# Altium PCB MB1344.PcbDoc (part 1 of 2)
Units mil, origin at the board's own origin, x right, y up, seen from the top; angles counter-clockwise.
Board outline 2760.94 x 3253.06 mil, 2 copper layers (Top Layer, Bottom Layer), stack 61.811 mil thick; 133 components, 124 nets, 521 pads, 490 vias.
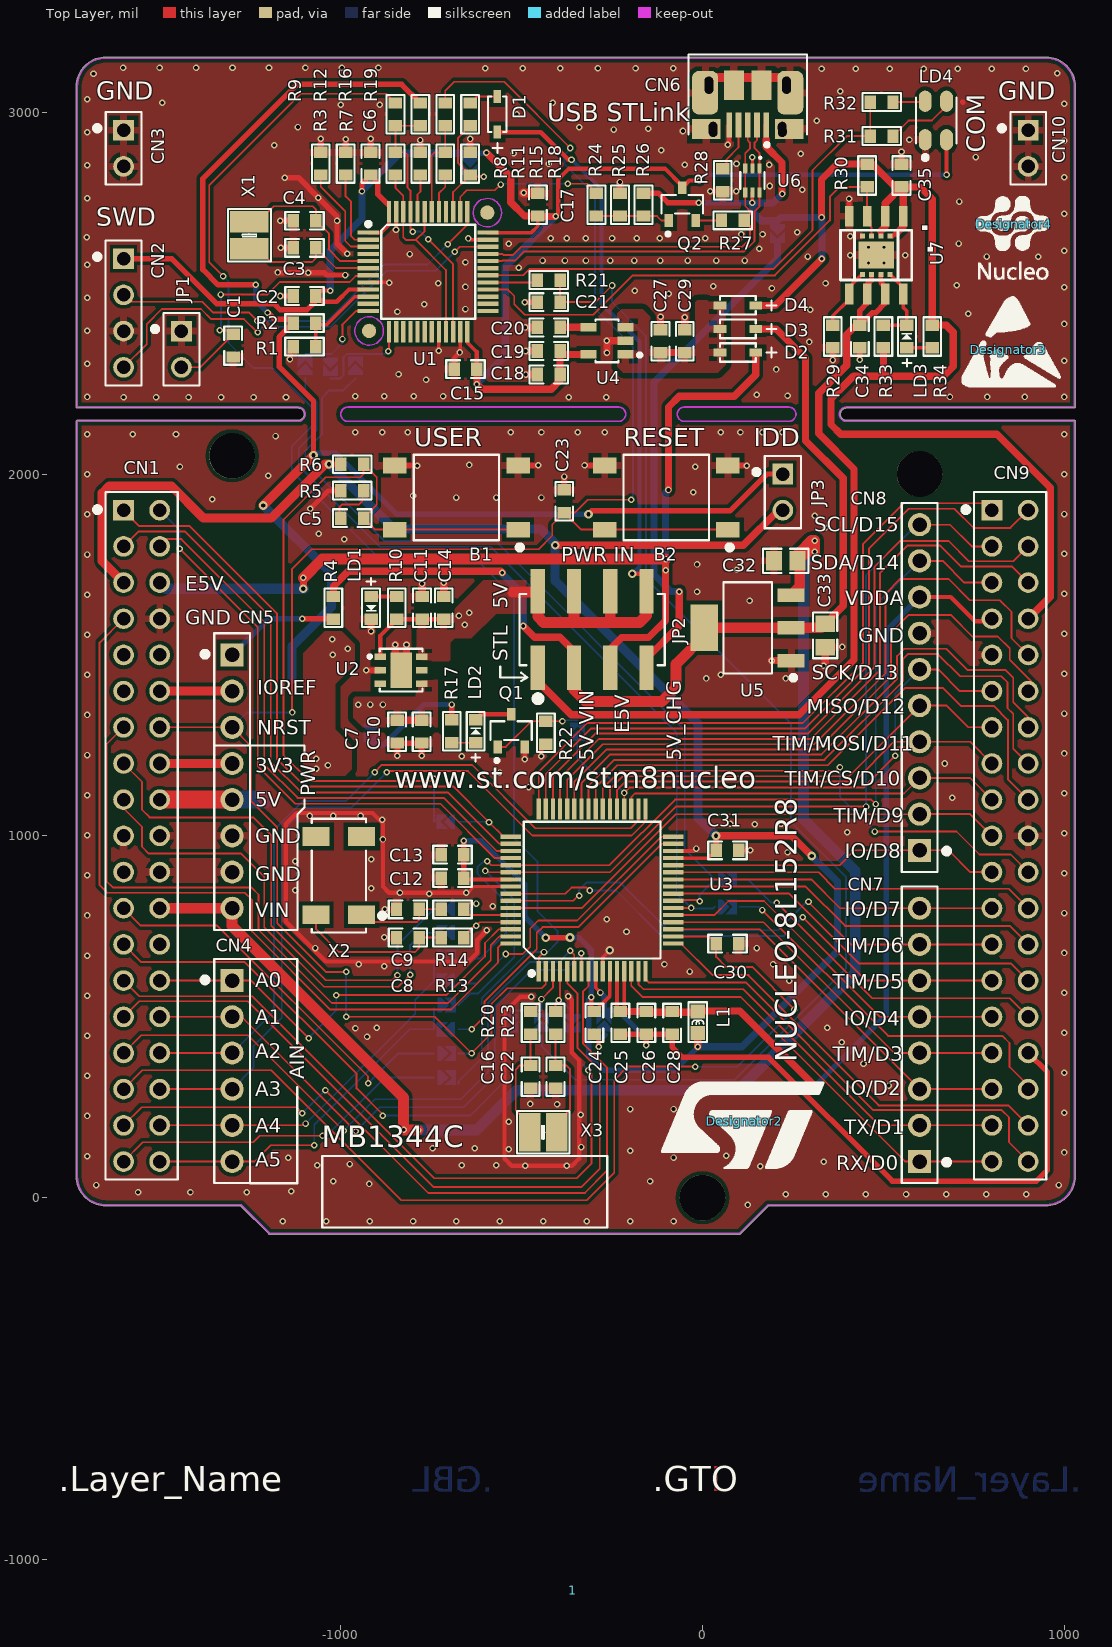
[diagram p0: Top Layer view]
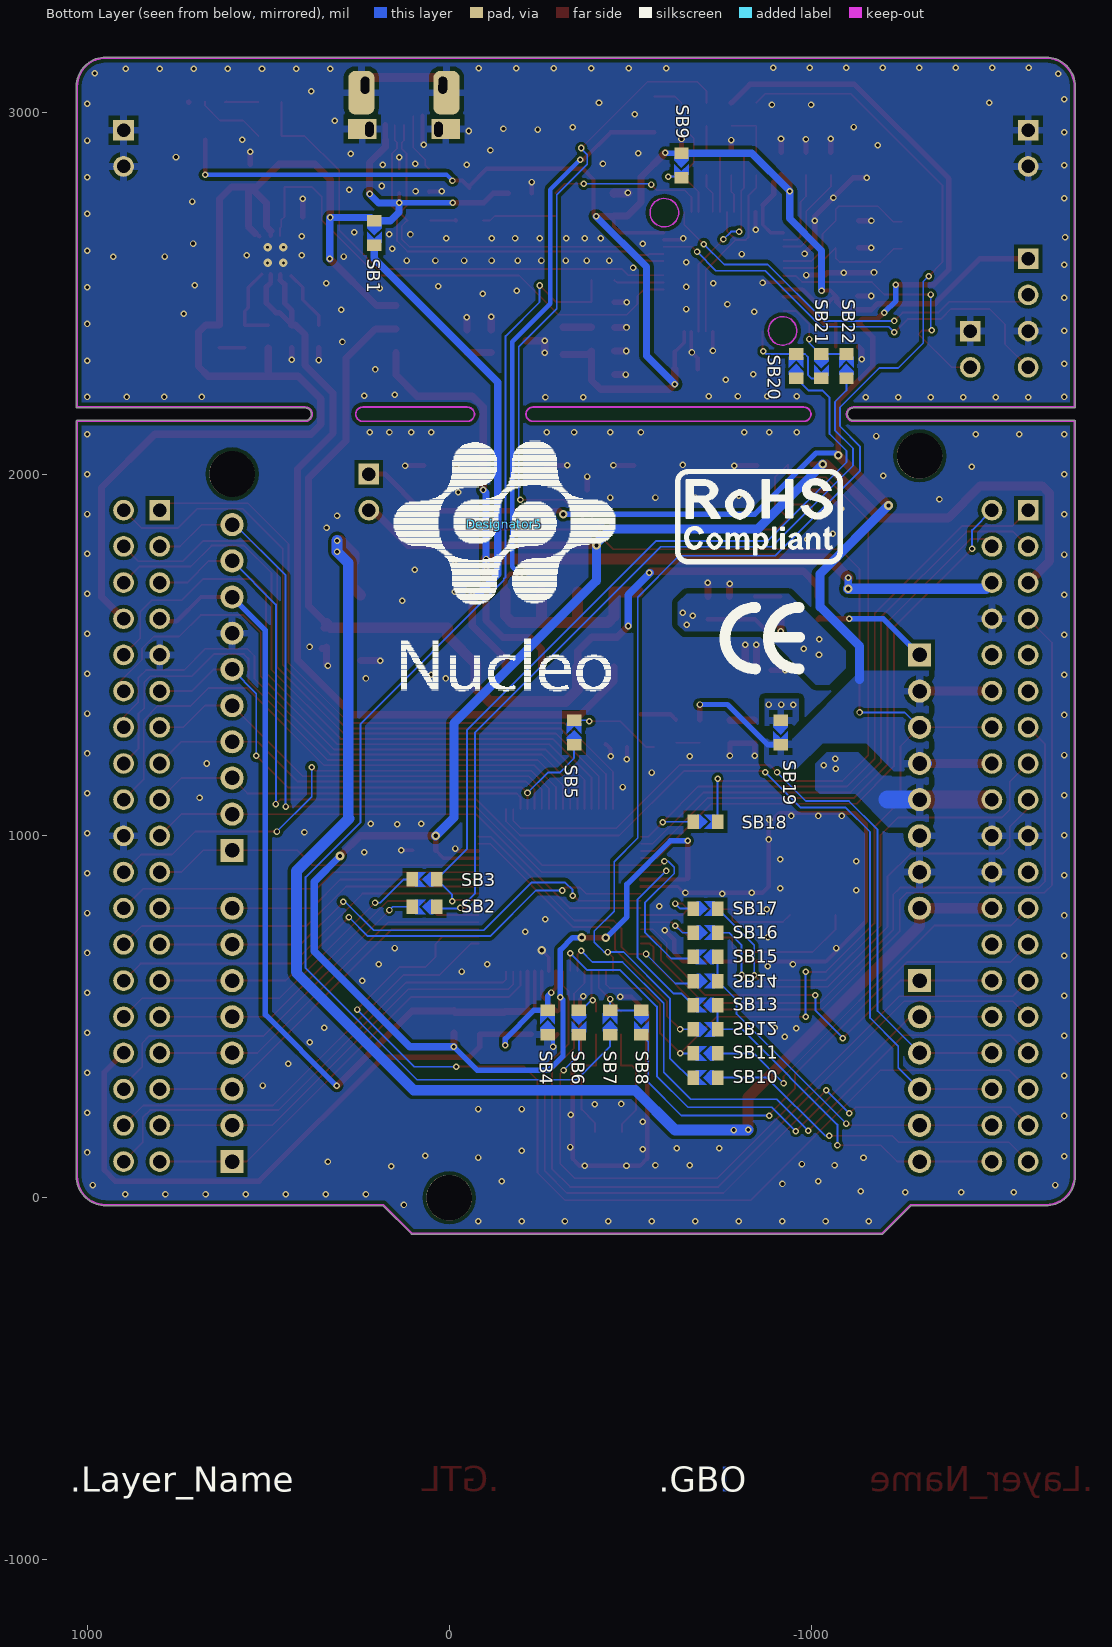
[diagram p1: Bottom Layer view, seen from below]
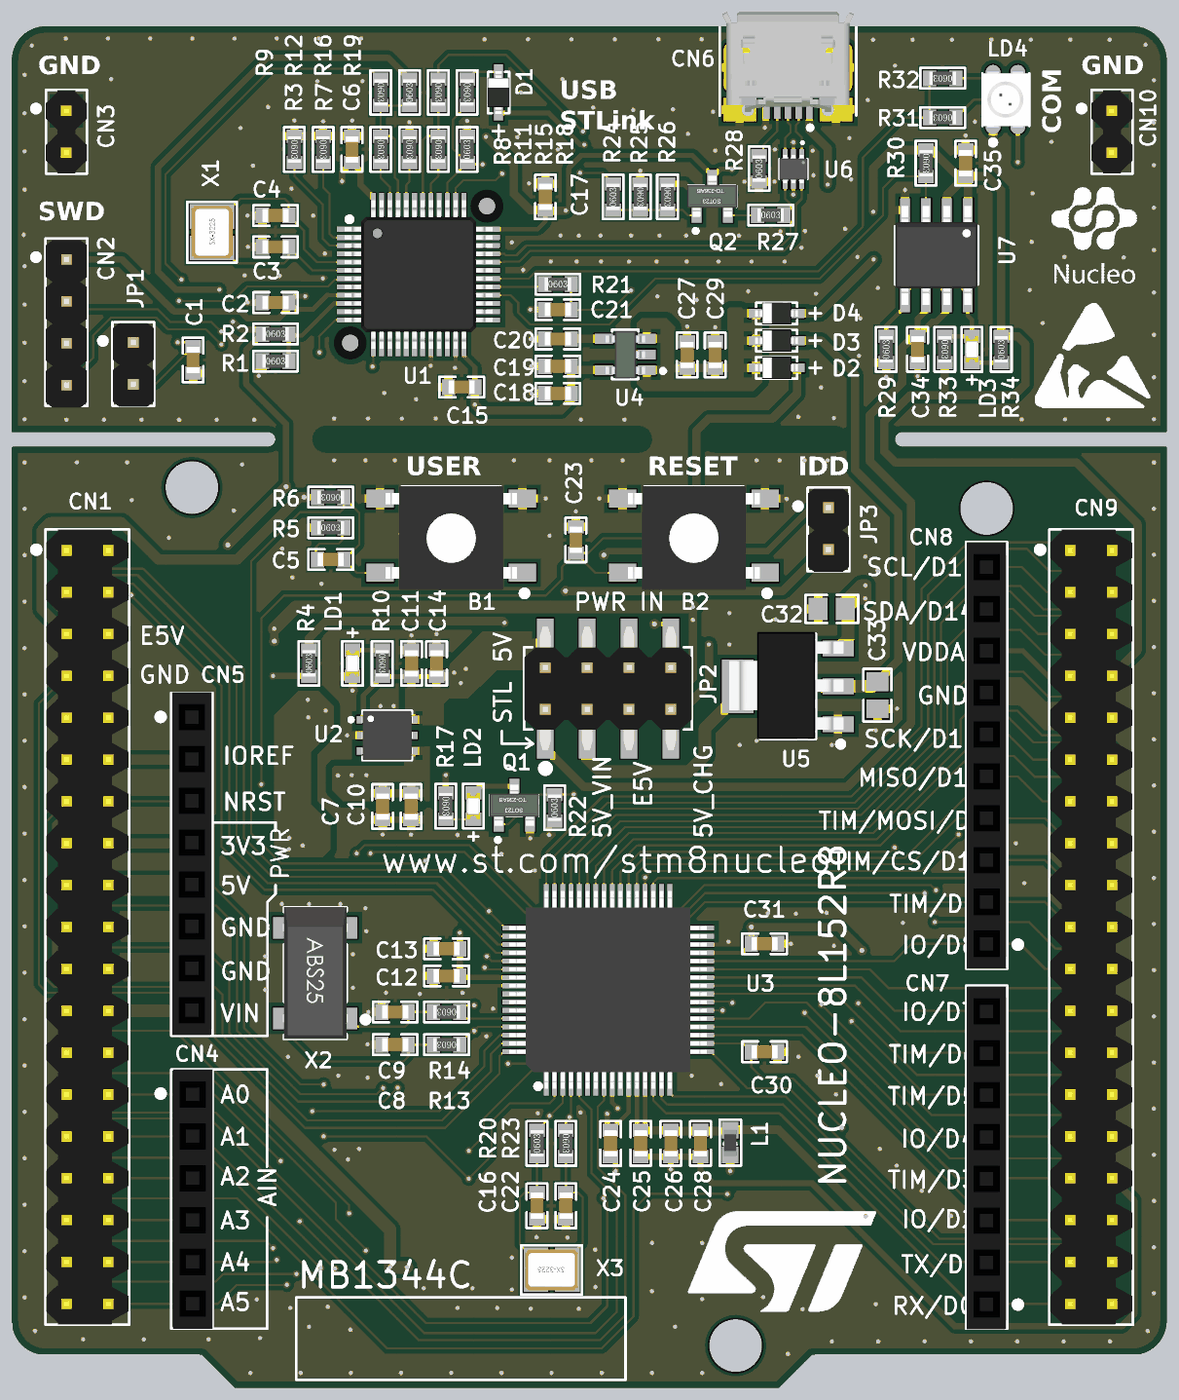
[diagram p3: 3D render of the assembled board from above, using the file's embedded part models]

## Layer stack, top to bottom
Top Solder: solder mask 0.5906, Solder Resist, Dk 3.5
Top Layer: signal copper 1.378
Dielectric 1: dielectric 59.0551, FR-4, Dk 4.8
Bottom Layer: signal copper 1.378
Bottom Solder: solder mask 0.5906, Solder Resist, Dk 3.5

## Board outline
-1730.47,59.05 ccw(c-1649.21,59.05) -1649.21,-22.2 ccw(c-1649.21,-19.69) -1649.17,-22.2 -1276.24,-22.2 -1198.24,-100.2 ccw(c-1196.46,-98.43) -1196.46,-100.94 102.76,-100.94 ccw(c102.76,-98.43) 104.53,-100.2 104.54,-100.19 cw(c102.76,-98.43) 104.52,-100.21 182.54,-22.2 949.21,-22.2 ccw(c949.21,59.06) 1030.47,59.06 1030.47,2145.67 ccw(c1027.95,2145.67) 1027.95,2148.18 398.03,2148.18 cw(c398.03,2165.35) 398.03,2182.52 1027.93,2182.52 ccw(c1027.95,2185.04) 1030.47,2185.04 1030.47,3070.87 ccw(c949.21,3070.87) 949.24,3152.12 ccw(c949.21,3070.87) 949.21,3152.12 cw(c949.21,3149.61) 949.24,3152.12 949.21,3152.12 -1649.21,3152.12 ccw(c-1649.21,3149.61) -1649.24,3152.12 cw(c-1649.21,3070.87) -1649.21,3152.12 -1649.24,3152.12 ccw(c-1649.21,3070.87) -1730.47,3070.87 -1730.47,2185.04 ccw(c-1727.95,2185.04) -1727.92,2182.52 -1117.72,2182.52 cw(c-1117.72,2165.35) -1100.55,2165.35 cw(c-1117.72,2165.35) -1117.72,2148.18 -1727.95,2148.18 ccw(c-1727.95,2145.67) -1730.47,2145.65

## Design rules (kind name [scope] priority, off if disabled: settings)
Clearance [All] p1: gap=7.87 ignorepadtopadclearanceinfootprint=FALSE except(0: Arc-Hole Track-Hole SMDPad-Hole THPad-Hole Via-Hole Fill-Hole Poly-Hole Region-Hole Text-Hole; 7: Region-Region; 8: Via-Poly; 10: Arc-Poly Arc-Region Track-Poly Track-Region SMDPad-Region THPad-Poly THPad-Region Via-Region Fill-Region Poly-Region; 12: SMDPad-Poly; 15: Fill-Poly Poly-Poly)
ComponentClearance [All] p1: gap=7.87 collisioncheckmode=3 verticalgap=7.87 showdistances=FALSE
DiffPairsRouting DiffPair_usb [InDifferentialPair('DifferentialPair1')] p1: maxlimit=10 minlimit=5 mostfreqgap=8 toplayer_minwidth=4 toplayer_maxwidth=6 toplayer_prefwidth=5 bottomlayer_minwidth=4 bottomlayer_maxwidth=6 bottomlayer_prefwidth=5 maxuncoupledlength=500
HoleSize [All] p1: absolutevalues=TRUE maxlimit=393.7 minlimit=1 maxpercent=80.000 minpercent=20.000
MatchedLengths DiffPair_usb_1 [InDifferentialPair ('NewDifferentialPair1')] p1: tolerance=50 checknetsindiffpair=TRUE checkdiffpairvsdiffpair=FALSE checkxsignals=FALSE checkothers=FALSE
MinimumSolderMaskSliver [All] p1: minsoldermaskwidth=0.8
PlaneConnect [All] p1: planeconnectstyle=Relief reliefexpansion=20 reliefentries=4 reliefconductorwidth=8.27 reliefairgap=8.27
PolygonConnect PolygonConnect_via [IsVia] p1: connectstyle=Direct reliefconductorwidth=10 reliefentries=4 polygonreliefangle="90 Angle" airgapwidth=10
PolygonConnect [All] p2: connectstyle=Relief reliefconductorwidth=20 reliefentries=4 polygonreliefangle="90 Angle" airgapwidth=12
RoutingVias [All] p1: holewidth=10 width=18 viastyle="Through Hole" minholewidth=8 minwidth=16 maxholewidth=12 maxwidth=24
SilkToSilkClearance [All] p1: silktosilkclearance=0
SilkToSolderMaskClearance [IsPad] p1: minsilkscreentomaskgap=1 clearancetoexposedcopper=TRUE
SolderMaskExpansion [All] p1: expansion=4
Width [All] p1: maxlimit=60 minlimit=5 preferedwidth=7.87 minimp=50.000000 maximp=50.000000 favimp=50.000000
23 further rules are at their usual default settings.

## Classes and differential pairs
net class PG[0..7]: PG0 PG1 PG2 PG3 PG4 PG5 PG6 PG7
net class PF[0..7]: PF0 PF1 PF4 PF5 PF6 PF7
net class PE[0..7]: PE0 PE1 PE2 PE3 PE4 PE5 PE6 PE7
net class PD[0..7]: PD0 PD1 PD2 PD3 PD4 PD5 PD6 PD7
net class PC[0..7]: PC0 PC1 PC2 PC3 PC4 PC5 PC6 PC7
net class PB[0..7]: PB0 PB1 PB2 PB3 PB4 PB5 PB6 PB7
net class PA[0..7]: PA0 PA1 PA2 PA3 PA4 PA5 PA6 PA7
component class "U_STM8L152R8T6 microcontroller power": C12 C13 C24 C25 C26 C28 C30 C31 L1 SB4
component class "U_STM8L152R8T6 microcontroller IOs": B1 B2 C5 C8 C9 C16 C22 C23 R5 R6 R13 R14 R20 R23 SB2 SB3 SB7 SB10 SB11 SB18 U3 X2 X3
component class U_ST-LinkV2_SWIM: C1 C2 C3 C4 C6 C15 C17 C18 C19 C20 C21 C27 C29 C34 C35 CN2 CN3 CN6 CN10 D1 D2 D3 D4 HW1 JP1 LD3 LD4 Q2 R1 R2 R3 R7 R8 R9 R11 R12 R15 R16 R18 R19 R21 R24 R25 R26 R27 R28 R29 R30 R31 R32 R33 R34 SB1 SB9 SB20 SB21 SB22 U1 U4 U6 U7 X1
component class U_Power: C7 C10 C11 C14 C32 C33 HW2 HW3 JP2 JP3 LD1 R10 SB19 U2 U5 U7
component class U_Arduino_extension_connectors: CN1 CN4 CN5 CN7 CN8 CN9 LD2 Q1 R4 R17 R22 SB5 SB6 SB8 SB12 SB13 SB14 SB15 SB16 SB17
component class Project_Overview: PCB
differential pair DifferentialPair1: +STLINK_USB_D_P -STLINK_USB_D_N

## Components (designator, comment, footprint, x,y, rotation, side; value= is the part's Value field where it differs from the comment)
1 "Comment" Sheetbox_2L2S -2134,-1295 r0 top
B1 "USER[BLUE]" SW4P600X600 -680,1935 r180 top
B2 "RESET[BLACK]" SW4P600X600 -100,1935 r180 top locked
C1 "C" C0603 -1297,2355 r90 top
C2 "C" C0603 -1100,2492 r0 top
C3 "C" C0603 -1100,2625 r180 top
C4 "C" C0603 -1100,2700 r180 top
C5 "C" C0603 -968,1878 r0 top
C6 "C" C0603 -917.33,2858 r270 top
C7 "C" C0603 -844,1288 r90 top
C8 "C" C0603 -814,719 r0 top
C9 "C" C0603 -814,797 r0 top
C10 "C" C0603 -776,1288 r90 top
C11 "C" C0603 -775,1630 r270 top
C12 "C" C0603 -691,883 r180 top
C13 "C" C0603 -691,948 r180 top
C14 "C" C0603 -715,1630 r270 top
C15 "C" C0603 -655,2290 r0 top
C16 "12PF" C0603 -475,334 r90 top
C17 "C" C0603 -455,2744.5 r270 top
C18 "C" C0603 -425,2275 r0 top
C19 "C" C0603 -425,2340 r0 top
C20 "C" C0603 -425,2405 r0 top
C21 "C" C0603 -425,2475 r0 top
C22 "12PF" C0603 -406,334 r90 top
C23 "C" C0603 -382,1925 r270 top
C24 "C" C0603 -299,482.97 r270 top
C25 "C" C0603 -227,482.97 r270 top
C26 "C" C0603 -155,482.97 r270 top
C27 "C" C0603 -116,2367 r270 top
C28 "C" C0603 -84,482.97 r270 top
C29 "C" C0603 -49,2367 r270 top
C30 "C" C0603 69,702 r0 top
C31 "C" C0603 69,960 r0 top
C32 "C" C0805 230,1760 r0 top
C33 "C" C0805 339,1554 r90 top
C34 "C" C0603 435,2380 r90 top
C35 "C" C0603 550,2825 r90 top
CN1 "2.54mm 2x19" HDRV38W64P254_2X19_4826X508X838P -1550,1000 r270 top locked
CN2 "SIP4" HDRV4W64P254_1X4_1016X254X854P -1600,2445 r270 top
CN3 "2.54mm 1X2" HDRV2W64P254_1X2_508X250X854P -1600,2900 r270 top
CN4 "SIP6" SOKV2W64P254_1X6_1574X250X850P -1300,350 r270 top locked
CN5 "SIP8" SOKV2W64P254_1X8_2082X250X850P -1300,1150 r270 top locked
CN6 "MICROUSB5_6" USB-MICRO-B-5P-SMD_800X560 125,2965 r180 top locked
CN7 "SIP8" SOKV2W64P254_1X8_2082X250X850P 600,450 r90 top locked
CN8 "SIP10" SOKV2W64P254_1X10_2590X250X850P 600,1410 r90 top locked
CN9 "2.54mm 2x19" HDRV38W64P254_2X19_4826X508X838P 850,1000 r270 top locked
CN10 "2.54mm 1X2" HDRV2W64P254_1X2_508X250X854P 900,2900 r270 top
D1 "D" SOD323 -567,2994 r270 top
D2 "D" SOD323 98,2336 r0 top
D3 "D" SOD323 98,2401 r0 top
D4 "D" SOD323 98,2466 r0 top
Designator1 "Comment" FIGURE_CROSS -4103,-2909 r0 top
Designator2 "Comment" ST_LOGO_10mm 116,211 r0 top
Designator3 "Comment" "LOGO ESD" 845,2344 r0 top
Designator4 "Comment" "NUCLEO_black 0.5cm" 860,2690 r0 top
Designator5 "Comment" "NUCLEO_black 2cm" -152,1861 r180 bottom
JP1 "SIP2" HDRV2W64P254_1X2_508X254X854P -1440,2345 r270 top locked
JP2 "2.54mm 2x4" HDRVS8W64P254_2X4_1016X750X850P -305,1570 r0 top locked
JP3 "SIP2" HDRV2W64P254_1X2_508X254X854P 222,1950 r270 top
L1 "L" L0603 -13,485 r90 top
LD1 "LED_green" D0603 -916,1630 r90 top
LD2 "LED_green" D0603 -627,1289 r270 top
LD3 "LED_red" D0603 565,2380 r270 top
LD4 "LED4_RED/GRN" PLCC150P350X280X210-4N 645,2977 r90 top
Q1 "NMOS" TO-236 -529,1291 r90 top
Q2 "NPN" TO-236 -56,2746 r90 top
R1 "R" R0603 -1100,2352 r0 top
R2 "R" R0603 -1100,2417 r0 top
R3 "R" R0603 -1055,2858 r270 top
R4 "R" R0603 -1020,1630 r90 top
R5 "R" R0603 -968,1954 r0 top
R6 "R" R0603 -968,2027 r180 top
R7 "R" R0603 -986.17,2858 r270 top
R8 "R" R0603 -848.5,2858 r270 top
R9 "R" R0603 -848.5,2994 r270 top
R10 "R" R0603 -845,1630 r270 top
R11 "R" R0603 -779.67,2858 r270 top
R12 "R" R0603 -779.67,2994 r90 top
R13 "R" R0603 -691,719 r180 top
R14 "R" R0603 -691,797 r180 top
R15 "R" R0603 -710.83,2858 r270 top
R16 "R" R0603 -710.83,2994 r270 top
R17 "R" R0603 -693,1289 r270 top
R18 "R" R0603 -642,2858 r90 top
R19 "R" R0603 -642,2994 r270 top
R20 "R" R0603 -475,482.97 r90 top
R21 "R" R0603 -425,2536 r0 top
R22 "R" R0603 -433,1285 r90 top
R23 "R" R0603 -406,482.97 r270 top
R24 "R" R0603 -293,2744.5 r90 top
R25 "R" R0603 -228,2744.5 r270 top
R26 "R" R0603 -163,2744.5 r270 top
R27 "R" R0603 84,2701 r0 top
R28 "R" R0603 56,2812 r90 top
R29 "R" R0603 360,2380 r90 top
R30 "R" R0603 455,2825 r270 top
R31 "R" R0603 495,2934 r180 top
R32 "R" R0603 495,3028 r180 top
R33 "R" R0603 500,2380 r270 top
R34 "R" R0603 635,2380 r90 top
SB1 "SB_ON" JP2_SMD 207,2666 r90 bottom
SB2 "SB_OFF" JP2_SMD 68,804 r180 bottom
SB3 "SB_OFF" JP2_SMD 68,879.53 r180 bottom
SB4 "SB_ON" JP2_SMD -272,483.75 r270 bottom
SB5 "SB_ON" JP2_SMD -345,1286 r270 bottom
SB6 "SB_OFF" JP2_SMD -358.33,483.75 r90 bottom
SB7 "SB_ON" JP2_SMD -444.67,483.75 r270 bottom
SB8 "SB_OFF" JP2_SMD -531,483.75 r90 bottom
SB9 "SB_OFF" JP2_SMD -642,2853 r90 bottom
SB10 "SB_ON" JP2_SMD -708,332 r180 bottom
SB11 "SB_ON" JP2_SMD -708,398.71 r180 bottom
SB12 "SB_ON" JP2_SMD -708,465.43 r0 bottom
SB13 "SB_OFF" JP2_SMD -708,532.14 r180 bottom
SB14 "SB_ON" JP2_SMD -708,598.86 r0 bottom
SB15 "SB_OFF" JP2_SMD -708,665.57 r180 bottom
SB16 "SB_OFF" JP2_SMD -708,732.28 r0 bottom
SB17 "SB_OFF" JP2_SMD -708,799 r0 bottom
SB18 "SB_ON" JP2_SMD -708,1039 r0 bottom
SB19 "SB_ON" JP2_SMD -916,1286 r90 bottom
SB20 "SB_ON" JP2_SMD -959,2298 r270 bottom
SB21 "SB_OFF" JP2_SMD -1028.5,2298 r90 bottom
SB22 "SB_ON" JP2_SMD -1098,2298 r270 bottom
U1 "STM32F103CBT6" QFP50P900X900X160-48N -758,2559 r0 top locked
U2 "LDL112PV33R" DFN300X300X80-7N -833,1458 r0 top
U3 "STM8L152R8T6" QFP50P1000X1000X160-64N -305,850 r90 top locked
U4 "LD3985M33R" SOT23-5 -264,2368 r180 top
U5 "LD1117S50TR" SOT-223 125,1575 r180 top
U6 "USBLC6-2P6" SOT-666 138,2811 r270 top
U7 "ST890" SOIC127P600X175-8N+PQFN65P300X300X90_HS-9N 480,2605 r270 top
X1 "X" XTAL320X250X100N -1252,2660 r90 top
X2 "MC306" OSCCC380X800X250-4N -1005,890 r180 top locked
X3 "8MHZ" XTAL320X250X100N -440,181 r180 top

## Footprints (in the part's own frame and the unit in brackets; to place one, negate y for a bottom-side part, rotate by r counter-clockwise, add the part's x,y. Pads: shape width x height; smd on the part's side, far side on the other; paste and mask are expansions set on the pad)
C0603 [mm]
  rect 0.8x0.95 smd mask+0.1: 1(-0.8,0) 2(0.8,0)
  Top Layer pour cut-out: -0.3,0.6 0.3,0.6 0.3,-0.6 -0.3,-0.6
  silkscreen extent -1.35,-0.63 1.35,0.63, body extent -0.8,-0.4 0.8,0.4, height 0.9
C0805 [mm] "Chip Capacitor, 2-Leads, Body 2.00x1.25mm, IPC Medium Density"
  rect 1.15x1.35 smd mask+0.1: 1(-0.825,0) 2(0.825,0)
  silkscreen extent -1.6,-0.85 1.6,0.85, body extent -1.05,-0.67 1.05,0.67, height 1.35
D0603 [mm]
  rect 0.8x0.95 smd mask+0.1: 1(-0.8,0) 2(0.8,0)
  Top Layer pour cut-out: -0.3,0.6 0.3,0.6 0.3,-0.6 -0.3,-0.6
  silkscreen extent -1.35,-0.63 2.1,0.63, body extent -0.8,-0.4 0.8,0.4, height 0.6
DFN300X300X80-7N [mm]
  rect 0.8x0.45 smd mask+0.1: 1(-1.45,0.95) 2(-1.45,0) 3(-1.45,-0.95) 4(1.45,-0.95) 5(1.45,0) 6(1.45,0.95)
  rect 1.5x2.5 smd mask+0.1: 7(0,0)
  silkscreen extent -2.25,-1.5 1.5,1.5, body extent -1.55,-1.5 1.55,1.5, height 0.75
FIGURE_CROSS [mil]
HDRV2W64P254_1X2_508X250X854P [mm]
  rect 1.45x1.45 hole 0.95 mask+0.1: 1(-1.27,0)
  round 1.45 hole 0.95 mask+0.1: 2(1.27,0)
  silkscreen extent -2.54,-2.01 2.54,1.25, body extent -2.54,-1.25 2.54,1.25, height 8.5
HDRV2W64P254_1X2_508X254X854P [mm]
  rect 1.45x1.45 hole 0.95 mask+0.1: 1(-1.27,0)
  round 1.45 hole 0.95 mask+0.1: 2(1.27,0)
  silkscreen extent -2.54,-2.01 2.54,1.27, body extent -2.49,-1.25 2.59,1.25, height 8.6
HDRV4W64P254_1X4_1016X254X854P [mm]
  rect 1.45x1.45 hole 0.95 mask+0.1: 1(-3.81,0)
  round 1.45 hole 0.95 mask+0.1: 2(-1.27,0) 3(1.27,0) 4(3.81,0)
  silkscreen extent -5.08,-2.01 5.08,1.27, body extent -4.98,-1.25 5.18,1.25, height 8.6
HDRV38W64P254_2X19_4826X508X838P [mm]
  rect 1.45x1.45 hole 0.95 mask+0.1: 1(-22.86,-1.27)
  round 1.45 hole 0.95 mask+0.1: 2(-22.86,1.27) 3(-20.32,-1.27) 4(-20.32,1.27) 5(-17.78,-1.27) 6(-17.78,1.27) 7(-15.24,-1.27) 8(-15.24,1.27) 9(-12.7,-1.27) 10(-12.7,1.27) 11(-10.16,-1.27) 12(-10.16,1.27) 13(-7.62,-1.27) 14(-7.62,1.27) 15(-5.08,-1.27) 16(-5.08,1.27) 17(-2.54,-1.27) 18(-2.54,1.27) 19(0,-1.27) 20(0,1.27) 21(2.54,-1.27) 22(2.54,1.27) 23(5.08,-1.27) 24(5.08,1.27) 25(7.62,-1.27) 26(7.62,1.27) 27(10.16,-1.27) 28(10.16,1.27) 29(12.7,-1.27) 30(12.7,1.27) 31(15.24,-1.27) 32(15.24,1.27) 33(17.78,-1.27) 34(17.78,1.27) 35(20.32,-1.27) 36(20.32,1.27) 37(22.86,-1.27) 38(22.86,1.27)
  silkscreen extent -24.13,-3.28 24.13,2.54, body extent -24.13,-2.5 24.13,2.5, height 8.5
HDRVS8W64P254_2X4_1016X750X850P [mm]
  rect 1x3.12 smd paste+0 mask+0.1: 1(-3.81,-2.69) 2(-3.81,2.69) 3(-1.27,-2.69) 4(-1.27,2.69) 5(1.27,-2.69) 6(1.27,2.69) 7(3.81,-2.69) 8(3.81,2.69)
  silkscreen extent -5.1,-5.06 5.1,2.5, body extent -5.08,-3.75 5.08,3.75, height 9.8
JP2_SMD [mil]
  rect 32x40 smd mask+3.94: 1(33.75,0) 2(-33.75,0)
  Top Layer region: 23.75,20 13.75,20 -6.25,0 13.75,-20 23.75,-20
  Top Layer region: -26.25,0 -16.25,0 3.75,20 -26.25,20
  Top Layer region: -26.25,0 -16.25,0 3.75,-20 -26.25,-20
L0603 [mm]
  rect 1x1 smd mask+0.1: 1(-0.75,0) 2(0.75,0)
  silkscreen extent -1.4,-0.65 1.4,0.65, body extent -0.8,-0.4 0.8,0.4, height 0.8
"LOGO ESD" [mil]
  silkscreen extent -127,-102 144,145
"NUCLEO_black 0.5cm" [mil]
  silkscreen extent -105,-152 99,78
"NUCLEO_black 2cm" [mil]
  silkscreen extent -305,-461 307,229
OSCCC380X800X250-4N [mm]
  rect 1.9x1.3 smd mask+0.1: 1(-1.6,2.75) 2(-1.6,-2.75) 3(1.6,-2.75) 4(1.6,2.75)
  silkscreen extent -3.16,-4 1.9,4, body extent -2,-4 2,4, height 2.7
PLCC150P350X280X210-4N [mm]
  oval 1.5x0.9 smd mask+0.1: 1(-1.35,0.75) 2(1.35,0.75) 3(1.35,-0.75) 4(-1.35,-0.75)
  silkscreen extent -2.71,-1.45 1.6,1.4, body extent -1.75,-1.4 1.75,1.4, height 1.9
QFP50P900X900X160-48N [mm]
  round 1 smd mask+0.5: 0(-4.15,-4.15) 0(4.15,4.15)
  rect 1.5x0.3 smd mask+0.05: 1(-4.2,2.75) 2(-4.2,2.25) 3(-4.2,1.75) 4(-4.2,1.25) 5(-4.2,0.75) 6(-4.2,0.25) 7(-4.2,-0.25) 8(-4.2,-0.75) 9(-4.2,-1.25) 10(-4.2,-1.75) 11(-4.2,-2.25) 12(-4.2,-2.75) 25(4.2,-2.75) 26(4.2,-2.25) 27(4.2,-1.75) 28(4.2,-1.25) 29(4.2,-0.75) 30(4.2,-0.25) 31(4.2,0.25) 32(4.2,0.75) 33(4.2,1.25) 34(4.2,1.75) 35(4.2,2.25) 36(4.2,2.75)
  rect 0.3x1.5 smd mask+0.05: 13(-2.75,-4.2) 14(-2.25,-4.2) 15(-1.75,-4.2) 16(-1.25,-4.2) 17(-0.75,-4.2) 18(-0.25,-4.2) 19(0.25,-4.2) 20(0.75,-4.2) 21(1.25,-4.2) 22(1.75,-4.2) 23(2.25,-4.2) 24(2.75,-4.2) 37(2.75,4.2) 38(2.25,4.2) 39(1.75,4.2) 40(1.25,4.2) 41(0.75,4.2) 42(0.25,4.2) 43(-0.25,4.2) 44(-0.75,4.2) 45(-1.25,4.2) 46(-1.75,4.2) 47(-2.25,4.2) 48(-2.75,4.2)
  Keep-Out Layer circle w0.1: c4.15,4.15 r1
  Keep-Out Layer circle w0.1: c-4.15,-4.15 r1
  silkscreen extent -4.25,-3.3 3.3,3.4, body extent -4.5,-4.5 4.5,4.5, height 1.5
QFP50P1000X1000X160-64N [mm]
  rect 1.45x0.3 smd paste+0 mask+0.05: 1(-5.7,3.75) 2(-5.7,3.25) 3(-5.7,2.75) 4(-5.7,2.25) 5(-5.7,1.75) 6(-5.7,1.25) 7(-5.7,0.75) 8(-5.7,0.25) 9(-5.7,-0.25) 10(-5.7,-0.75) 11(-5.7,-1.25) 12(-5.7,-1.75) 13(-5.7,-2.25) 14(-5.7,-2.75) 15(-5.7,-3.25) 16(-5.7,-3.75) 33(5.7,-3.75) 34(5.7,-3.25) 35(5.7,-2.75) 36(5.7,-2.25) 37(5.7,-1.75) 38(5.7,-1.25) 39(5.7,-0.75) 40(5.7,-0.25) 41(5.7,0.25) 42(5.7,0.75) 43(5.7,1.25) 44(5.7,1.75) 45(5.7,2.25) 46(5.7,2.75) 47(5.7,3.25) 48(5.7,3.75)
  rect 0.3x1.45 smd paste+0 mask+0.05: 17(-3.75,-5.7) 18(-3.25,-5.7) 19(-2.75,-5.7) 20(-2.25,-5.7) 21(-1.75,-5.7) 22(-1.25,-5.7) 23(-0.75,-5.7) 24(-0.25,-5.7) 25(0.25,-5.7) 26(0.75,-5.7) 27(1.25,-5.7) 28(1.75,-5.7) 29(2.25,-5.7) 30(2.75,-5.7) 31(3.25,-5.7) 32(3.75,-5.7) 49(3.75,5.7) 50(3.25,5.7) 51(2.75,5.7) 52(2.25,5.7) 53(1.75,5.7) 54(1.25,5.7) 55(0.75,5.7) 56(0.25,5.7) 57(-0.25,5.7) 58(-0.75,5.7) 59(-1.25,5.7) 60(-1.75,5.7) 61(-2.25,5.7) 62(-2.75,5.7) 63(-3.25,5.7) 64(-3.75,5.7)
  silkscreen extent -5.95,-4.8 4.8,4.8, body extent -6,-6 6,6, height 1.56
R0603 [mm]
  rect 0.8x0.95 smd mask+0.1: 1(-0.8,0) 2(0.8,0)
  Top Layer pour cut-out: -0.3,0.6 0.3,0.6 0.3,-0.65 -0.3,-0.65
  silkscreen extent -1.35,-0.63 1.35,0.63, body extent -0.8,-0.4 0.8,0.4, height 0.45
Sheetbox_2L2S [mil] "Sheetbox 2 layers / 2 silkscreens"
  round 20 on Mech16: 1(813.78,210.69) 1(2736.9,210.69)
SOD323 [mm]
  rect 0.9x0.55 smd mask+0.1: 1(-1.25,0) 2(1.25,0)
  silkscreen extent -1.25,-0.65 2.7,0.65, body extent -1.3,-0.67 1.3,0.68, height 1.1
SOIC127P600X175-8N+PQFN65P300X300X90_HS-9N [mm]
  rect 1.45x0.6 smd: 1(-2.725,1.905) 2(-2.725,0.635) 3(-2.725,-0.635) 4(-2.725,-1.905) 5(2.725,-1.905) 6(2.725,-0.635) 7(2.725,0.635) 8(2.725,1.905)
  rect 0.35x0.35 smd: 1(-1.35,0.975) 2(-1.35,0.325) 3(-1.35,-0.325) 4(-1.35,-0.975) 5(1.35,-0.975) 6(1.35,-0.325) 7(1.35,0.325) 8(1.35,0.975)
  rect 1.9x2.5 smd: 9(0,0)
  silkscreen extent -1.75,-2.5 1.75,2.5, body extent -3,-2.5 3,2.5, height 1.75
SOKV2W64P254_1X6_1574X250X850P [mm]
  rect 1.62x1.62 hole 1.02 mask+0.1: 1(-6.35,0)
  round 1.62 hole 1.02 mask+0.1: 2(-3.81,0) 3(-1.27,0) 4(1.27,0) 5(3.81,0) 6(6.35,0)
  silkscreen extent -7.87,-2.08 7.87,1.25, body extent -7.87,-1.15 7.87,1.25, height 8.5
SOKV2W64P254_1X8_2082X250X850P [mm]
  rect 1.62x1.62 hole 1.02 mask+0.1: 1(-8.89,0)
  round 1.62 hole 1.02 mask+0.1: 2(-6.35,0) 3(-3.81,0) 4(-1.27,0) 5(1.27,0) 6(3.81,0) 7(6.35,0) 8(8.89,0)
  silkscreen extent -10.41,-2.08 10.41,1.25, body extent -10.45,-1.2 10.37,1.2, height 8.5
SOKV2W64P254_1X10_2590X250X850P [mm]
  rect 1.62x1.62 hole 1.02 mask+0.1: 1(-11.43,0)
  round 1.62 hole 1.02 mask+0.1: 2(-8.89,0) 3(-6.35,0) 4(-3.81,0) 5(-1.27,0) 6(1.27,0) 7(3.81,0) 8(6.35,0) 9(8.89,0) 10(11.43,0)
  silkscreen extent -12.95,-2.08 12.95,1.25, body extent -12.95,-1.2 12.95,1.2, height 8.5
SOT23-5 [mm]
  rect 1.1x0.6 smd mask+0.1: 1(-1.3,0.95) 2(-1.3,0) 3(-1.3,-0.95) 4(1.3,-0.95) 5(1.3,0.95)
  silkscreen extent -2.35,-1.5 0.8,1.5, body extent -1.21,-1.44 1.19,1.46, height 1.09
SOT-223 [mm]
  rect 1.9x0.95 smd mask+0.1: 1(-3.05,2.3) 2(-3.05,0) 3(-3.05,-2.3)
  rect 1.9x3.25 smd mask+0.1: 4(3.05,0)
  silkscreen extent -3.34,-3.2 1.7,3.65, body extent -3.38,-3.3 3.58,3.2, height 1.9
SOT-666 [mm]
  rect 0.7x0.3 smd mask+0.1: 1(-0.85,0.5) 2(-0.85,0) 3(-0.85,-0.5) 4(0.85,-0.5) 5(0.85,0) 6(0.85,0.5)
  silkscreen extent -1.65,-0.85 0.6,0.85, body extent -0.85,-0.85 0.85,0.85, height 0.6
ST_LOGO_10mm [mil]
  silkscreen extent -230,-130 220,110
SW4P600X600 [mm]
  rect 1.65x1.1 smd mask+0.1: 1(-4.325,2.25) 2(4.325,2.25) 3(4.325,-2.25) 4(-4.325,-2.25)
  silkscreen extent -4.61,-3 3,3.66, body extent -4,-3 4,3.3, height 7.3
TO-236 [mm]
  rect 0.9x0.6 smd mask+0.1: 1(-1.15,0.95) 2(-1.15,-0.95) 3(1.15,0)
  silkscreen extent -2.15,-1.45 0.65,1.45, body extent -1.25,-1.5 1.25,1.5, height 1.09
USB-MICRO-B-5P-SMD_800X560 [mm]
  rect 0.4x1.75 smd mask+0.1: 1(-1.3,0) 2(-0.65,0) 3(0,0) 4(0.65,0) 5(1.3,0)
  rect 2x1.4 hole 0.6 slot 1.05 at 90.65 deg copper offset -0.5,-0.02 paste+0 mask+0.1: 6(-2.425,0.32)
  rect 2x1.4 hole 0.6 slot 1.05 at 90.65 deg copper offset 0.5,-0.02 paste+0 mask+0.1: 7(2.425,0.32)
  rrect50% 1.825x3.05 hole 0.6 slot 1.2 at 90.7 deg copper offset -0.262,0.525 paste+0 mask+0.1: 8(-2.725,-2.78)
  rrect50% 1.825x3.05 hole 0.6 slot 1.2 at 90.7 deg copper offset 0.262,0.525 paste+0 mask+0.1: 9(2.725,-2.78)
  rect 1.4x2.1 smd paste+0 mask+0.1: 10(-0.975,-2.78) 11(0.975,-2.78)
  silkscreen extent -4.15,-4.95 4.15,1.51, body extent -3.99,-5.61 3.99,0.45, height 2.74
XTAL320X250X100N [mm]
  rect 1.5x2.7 smd mask+0.1: 1(-0.95,0) 2(0.95,0)
  silkscreen extent -1.85,-1.5 1.85,1.5, body extent -1.6,-1.25 1.6,1.25, height 0.81

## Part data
B1: library part 1010001100062, "tact switch,blue,6*6,SMT,180,CTSM-644B-V-T/R,(TD-0341X-GO0）"
B2: library part 1010001100063, "tact switch,black,6*6,SMT,180,CTSM-644N-V-T/R,(TD-0341X-A00）"
C1 C2 C5 C6 C7 C11 C12 C15 C17 C18 C23 C24 C25 C26 C29 C31 C34: library part 1004001100110, "CAP,100NF,+/-10%,X7R,50V,SMD0603"
C3 C4 C16 C22: library part 1004001100897, "CAP,12PF,+/-5%,NPO,50V,SMD0603"
C8 C9 C21: library part 1004001100069, "CAP,20PF,+/-5%,C0G,50V,SMD0603"
C10 C13 C14 C19 C27 C28 C30 C35: library part 1004001100120, "CAP,1UF,+/-10%,X7R,16V,SMD0603"
C20: library part 1004001100103, "CAP,10NF,+/-10%,X7R,50V,SMD0603"
C32 C33: library part 1004001100159, "CAP,10UF,+/-10%,X5R,16V,SMD0805"
CN1 CN9: library part 1009001200377, "Connector,Pin Header,Straight,Male,2.54MM pitch,2x19P,6.0mm,10mm,Au Over 50u\"NI, black,DIP"
CN2: library part 1009001200307, "Connector,Pin Header,Straight,Male,1x4Pin,2.54MM pitch,6.0,3.0,Au over 50 u nickle , black,DIP"
CN3 CN10: library part 1009001200378, "Connector,Pin Header,Straight,Male,2.54MM pitch,1x2P,6.0mm,10mm,Au Over 50u\"NI, black,DIP"
CN4: library part 1009002200189, "Connector,Pin Socket,Straight,Female,1x6Pin,2.54MM pitch,8.5,9.92,Gold Flash 1u, black,DIP"
CN5 CN7: library part 1009002200162, "Connector,Pin Socket,Straight,Female,1x8Pin,2.54MM pitch,8.5,9.92,Gold Flash 1u, black,DIP"
CN6: library part 1009007100040R2, "Connector,MicroUSB B port,5 Position,Right Angle,Gold Flash 1u, black,SMD"
CN8: library part 1009002200163, "Connector,Pin Socket,Straight,Female,1x10Pin,2.54MM pitch,8.5,9.92,Gold Flash 1u, black,DIP"
D1 D2 D3 D4: library part 1006002100076C, "DIODE SCHOTTKY,BAT60JFILM,10V,3A, SOD323/A,ST,(X3 Code 9151097)"
JP1 JP3: library part 1009001200085R1, "Connector,Pin Header,Straight,Male,1x2Pin,2.54MM pitch,6.0,3.0,Au over 50 u nickle , black,DIP"
JP2: library part 1009001100223, "Connector,Pin Header,Straight,Male,2x4Pin,2.54MM pitch,6.0mm,Gold Flash  Over NI,black,SMD"
L1: library part 1005005100118, "Ferrite Bead,600ohm@100MHz,+/-25%,1000mA,0.2ohm,SMD0603"
LD1 LD2: library part 1006001100094, "LED,Yellow-Green,Water clear,20mA,0603,573nm,Vf:2.0v;"
LD3: library part 1006001100139, "LED,Briliant Red,WATER CLEAR,0603 TR"
LD4: library part 1006001100098, "LED IND RED/GRN TOP MOUNT 4PLCC,3.2*2.8MM"
Q1: library part 1006015100003, "Mosfet,N-Channel,2N7002,60V,115mA,SOT-23,SMD"
Q2: library part 1006013100039, "Trans,NPN,MMBT9013G-I-AE3-R,Ic:500mA,Vceo:20v, SOT-23,SMD"
R1 R2 R6 R18: library part 1003001100221, "RES,4K7,+/-5%,1/10W,SMD0603"
R3 R7 R26 R30: library part 1003001100235, "RES,10K,+/-5%,1/10W,SMD0603"
R4 R34: library part 1003001100202, "RES,1K,+/-5%,1/10W,SMD0603"
R5 R21 R24: library part 1003001100186, "RES,100R,+/-5%,1/10W,SMD0603"
R8 R15: library part 1003001100192, "RES,220R,+/-5%,1/10W,SMD0603"
R9 R16: library part 1003001100178, "RES,47R,+/-5%,1/10W,SMD0603"
R10 R17: library part 1003001100424, "RES,510R,+/-5%,1/10W,SMD0603"
R11 R28 R33: library part 1003001100269, "RES,100K,+/-5%,1/10W,SMD0603"
R12: library part 1003001100200, "RES,680R,+/-5%,1/10W,SMD0603"
R13 R14 R20 R23: library part 1003001100161, "RES,0R,+/-5%,1/10W,SMD0603"
R19: library part 1003001100467, "RES,2K7,+/-1%,1/10W,SMD0603"
R22: library part 1003001100291, "RES,1M,+/-5%,1/10W,SMD0603"
R25: library part 1003001100368, "RES,36K, +/-1%,1/10W,SMD0603"
R27: library part 1003001100207, "RES,1K5,+/-5%,1/10W,SMD0603"
R29: library part 1003001100211, "RES,2K2,+/-1%,1/10W,SMD0603"
R31 R32: library part 1003001100196, "RES,330R,+/-5%,1/10W,SMD0603"
SB1 SB4 SB5 SB7 SB10 SB11 SB12 SB14 SB18 SB19 SB20 SB22: library part PN029, "RES,0R,+/-5%,1/10W,SMD0603"
SB2 SB3 SB6 SB8 SB9 SB13 SB15 SB16 SB17 SB21: library part PN034, "RES,0R,+/-5%,1/10W,SMD0603"
U1: library part 1002001100035C, "IC, ARM Cortex-M3 MCU,STM32F103CBT6,LQFP-48,SMD,TR,(9175111),customer supply"
U2: library part 1002006100237C, "IC,LDO,1.2 A low quiescent current LDO with reverse current protection 3.3V,LDL112PV33R,DFN3x3,SMD"
U3: library part 1002002100257C, "IC,MCU 8-bit 64KB FLASH 3.3V,STM8L152R8T6,LQFP64, SMD"
U4: library part 1002006100166C, "IC,LDO,3.3V,LD3985M33R,SOT23-5L,ST,(X3 Code 9176161)"
U5: library part 1002006100169C, "IC,LDO,5V,LD1117S50TR,SOT223,STMicroelectronics,9176133"
U6: library part 1002020100274C, "IC,ESD Protection for High Speed Interface Protection 2.5 PF Low Cap,USBLC6-2P6, SOT-666,SMD,TR"
U7: library part 1002004100103C, "IC PWR SWITCH,ST890CDR,SO-8,ST,(X3 Code 9172002)"
X1 X3: library part 1008002100145C, "CRYSTAL, 8pF, -+50PPM,NX3225GD-8MHz-EXS00A-CG04874,SMT"
X2: library part 1008002100059, "Crystal,ABS25-32.768KHZ-T,32.768KHz,+/-20PPM,12.5PF,8 x3.8MM,SMD"

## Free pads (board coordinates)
  round 125.98 hole 125.98 unplated: 0(-1300,2050) 0(0,0) 0(600,2000)

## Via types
v1: diameter 18, hole 10, Top Layer to Bottom Layer, tented both sides, 474 vias
v2: diameter 24, hole 12, Top Layer to Bottom Layer, tented both sides, 12 vias
v3: diameter 23.62, hole 7.87, Top Layer to Bottom Layer, 4 vias

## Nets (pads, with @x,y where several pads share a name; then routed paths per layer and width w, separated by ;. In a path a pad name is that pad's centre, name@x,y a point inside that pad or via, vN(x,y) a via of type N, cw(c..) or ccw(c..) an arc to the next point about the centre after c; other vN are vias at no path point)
3V3: CN1.12 CN1.16 CN5.2 CN5.4 JP3.1 R2.1 R12.2 R17.1 SB19.2 | length 4699.6
  Top Layer w15: v1(-1234.37,2522.63) -1338.63,2522.63 -1380.87,2564.87 -1380.87,2816.13 -1120,3077 -831.17,3077 R12.2@-779.67,3025.5 ; v1(-1202,2446) -1201,2446 -1183,2428 -1142.5,2428 R2.1@-1131.5,2417 -1170,2378.5 -1170,2297 -1075,2202 v2(-1075,2052) ; R17.1@-693,1320.5 v1(-693,1363) ; v2(-315,1889) -306,1898 76,1898 178,2000 JP3.1@222,2000
  Top Layer w25: CN1.16@-1500,1200 CN5.4@-1300,1200 ; CN1.12@-1500,1400 CN5.2@-1300,1400 ; v2(-1214,1913) v2(-1075,2052)
  Bottom Layer w15: v1(-1234.37,2522.63) -1234.37,2478.37 v1(-1202,2446) ; v2(-1075,2052) -1069,2058 -1014,2058 -845,1889 v2(-315,1889) ; SB19.2@-916,1252.25 -879.98,1252.25 -769.23,1363 v1(-693,1363)
  Bottom Layer w25: CN1.16@-1500,1200 CN1.16@-1489,1200 ; CN5.4@-1322,1200 CN5.4@-1300,1200 ; v2(-1214,1913) -1025,1724 -1025,1633 -1134,1524 -1134,1432
3V3_STLINK: C2.2 C6.2 C15.2 C17.2 C18.2 C19.2 CN2.1 LD4.4 Q2.3 SB9.1 U1.1 U1.9 U1.24 U1.36 U1.48 U4.5 | length 4718.7
  Top Layer w10: -977,2509.79 U1.9@-923.35,2509.79 ; U1.1@-923.35,2667.27 -887.73,2667.27 -866.27,2688.73 U1.48@-866.27,2724.35 -866.27,2742.27 U1.48@-867.86,2743.86 ; U1.24@-649.73,2393.65 -649.73,2363.73 -623.5,2337.5 ; U1.36@-592.65,2667.27 -472.73,2667.27 -455,2685 C17.2@-455,2713
  Top Layer w12: C2.2@-1068.5,2492 -1053.5,2507 v1(-1029,2507) ; C2.2@-1066,2492 -1050,2476 -1010.79,2476 -977,2509.79 ; C15.2@-623.5,2290 -623.5,2337.5 ; v1(-406,2712) -399,2719 -399,2814 -369,2844 -103.72,2844 -56,2796.28 Q2.3@-56,2791.28 -36.28,2811 v1(-9,2811) ; v1(674.53,2827.47) LD4.4@674.53,2923.85
  Top Layer w15: CN2.1@-1600,2595 -1467,2595 -1343,2471 -1184,2471 -1167,2454 -1093,2454 -1071.5,2475.5 C2.2@-1071.5,2486.5 ; v1(-941,2782) -941,2802.84 C6.2@-917.33,2826.5 -896.86,2806.03 -896.86,2772.86 U1.48@-867.86,2743.86
  Top Layer w20: C15.2@-623.5,2290 v1(-623.5,2248.5) -609,2234 -418,2234 -393.5,2258.5 C18.2@-393.5,2275 C19.2@-393.5,2340 -384.1,2330.6 U4.5@-315.18,2330.6 ; v1(-597,2888) -530,2821 -530,2751 -492,2713 C17.2@-455,2713 -454,2712 v1(-406,2712)
  Bottom Layer w12: v1(-9,2811) 7.47,2827.47 v1(674.53,2827.47)
  Bottom Layer w15: SB9.1@-642,2886.75 -598.25,2886.75 v1(-597,2888)
  Bottom Layer w20: v1(-1029,2507) -1029,2618 -941,2706 v1(-941,2782) -836.25,2886.75 SB9.1@-642,2886.75 ; v1(-623.5,2248.5) -545,2327.01 -545,2573 v1(-406,2712)
5V: C11.2 C14.2 CN1.18 CN5.5 D1.2 JP2.2 JP2.4 JP2.6 JP2.8 R10.2 U2.1 U2.6 | length 2775.8
  Top Layer w12: U2.1@-890.09,1495.4 -890.09,1553.42 R10.2@-845,1598.5 C11.2@-775,1598.5 C14.2@-715,1598.5 ; D1.2@-567,2944.79 -446.79,2944.79 -371,2869 v1(-362,2869) ; v2(-194,1724) -168,1724 -155,1711 JP2.8@-155,1674.33
  Top Layer w30: -524,1674 -523.67,1674.33 -455,1674.33 -455,1606 -439,1590 -355,1590 ; JP2.4@-355,1674.33 -355,1590 ; JP2.6@-255,1674.33 -255,1591 -254,1590 ; JP2.8@-155,1674.33 -155,1609 -174,1590 -254,1590 ; -355,1590 -254,1590
  Top Layer w50: CN1.18@-1500,1100 CN5.5@-1300,1100
  Bottom Layer w12: v1(-362,2869) -279,2786 -279,2470.84 -174,2365.84 -174,1744 v2(-194,1724)
  Bottom Layer w50: CN5.5@-1300,1100 -1211,1100
  other v1: -1068,1186 -1035,1195 -1067,1213 -1022,1501 -980,1517 -1023,1543 -657,1583 -673,1608 -645,1617
5V_STLINK: C35.1 CN6.1 CN9.8 D4.2 R26.1 R30.1 R33.2 R34.2 SB1.1 U6.5 U7.1 U7.2 | length 4094.9
  Top Layer w10: v1(138,2750) U6.5@138,2777.54
  Top Layer w12: U7.2@492.8,2658.15 492.8,2671.8 ; U7.1@525,2657 530.09,2662.09 533.09,2662.09 536,2665
  Top Layer w15: R26.1@-163,2775.99 -121.99,2775.99 -96,2750 v1(-10,2750) ; 176.18,2924 CN6.1@176.18,2965
  Top Layer w20: D4.2@147.21,2466 201,2466 v1(330,2595) ; 176.34,2924 176.34,2904.66 220,2861 v1(220,2774) ; v1(329,2709) 329,2814 371.5,2856.5 R30.1@455,2856.5 469.5,2856.5 532.5,2793.5 C35.1@550,2793.5 ; 492.8,2671.8 505,2684 505,2748.5 C35.1@550,2793.5 ; R33.2@500,2348.5 500,2270 ; 536,2665 555,2684 C35.1@555,2788.5 ; CN9.8@900,1600 961,1661 961,1963 814,2110 382,2110 355,2137 355,2208 417,2270 500,2270 ; 500,2270 666,2270 693,2297 693,2392 673.5,2411.5 R34.2@635,2411.5 635,2760 601.5,2793.5 C35.1@550,2793.5
  Bottom Layer w15: v1(-10,2750) v1(138,2750)
  Bottom Layer w20: v1(138,2750) v1@138.87,2749.13 ; v1(220,2774) 195.13,2749.13 v1@138.87,2749.13 ; v1(330,2595) 330,2708 v1(329,2709) 216.25,2709 SB1.1@207,2699.75 162.25,2699.75 138.87,2723.13 v1@138.87,2749.13
5V_STLINK_SW: C34.2 JP2.1 U7.6 U7.7 | length 2365.9
  Top Layer w12: 467.2,2536.2 U7.6@467.2,2551.85 ; U7.7@492.8,2551.85 492.8,2529.2 U7.7@495.75,2526.25
  Top Layer w15: 467.2,2536.2 455,2524 U7.6@455,2497.72 455,2472 435,2452 C34.2@435,2411.5 469.5,2446 479,2446 505,2472 505,2517 U7.7@495.75,2526.25
  Top Layer w20: JP2.1@-455,1465.67 -455,1427 -363,1335 267,1335 419,1487 419,2014 321,2112 321,2223 398.43,2300.43 398.43,2385.43 424.5,2411.5 C34.2@435,2411.5
5V_USB_CHG: JP2.7 SB1.2 | length 1388
  Top Layer w20: JP2.7@-155,1465.67 -155,1490 -64,1581 v1(-64,1675)
  Bottom Layer w20: v1(-64,1675) -87,1675 -134,1722 -134,2253.75 207,2594.75 SB1.2@207,2632.25
5V_VIN: C33.2 D3.2 JP2.3 R4.2 U5.2 U5.4 | length 2786.8
  Top Layer w20: R4.2@-1020,1661.5 -1020,1690 -979,1731 -557,1731 v1(-552.94,1726.94) ; v1(-495,1580) -464,1549 -394,1549 -355,1510 JP2.3@-355,1465.67 ; D3.2@147.21,2401 204,2401 285,2320 285,2092 388.78,1988.22 388.78,1636.26 C33.2@339,1586.48 ; C33.2@339,1575 C33.2@345,1575
  Top Layer w30: JP2.3@-355,1465.67 -355,1404 -322,1371 -112,1371 -73.5,1409.5 -73.5,1474.5 4.92,1552.92 U5.4@4.92,1575 U5.2@245.08,1575 327.52,1575 C33.2@339,1586.48
  Bottom Layer w20: v1(-552.94,1726.94) -555.94,1726.94 -495,1666 v1(-495,1580)
AGND: C25.2 C26.2 C28.2 CN9.32 SB4.2 U3.9 | length 2042.2
  Top Layer w10: U3.9@-295.16,625.59 -295.16,580.16 v1(-282,567)
  Top Layer w15: C25.2@-227,451.47 C26.2@-155,451.47 ; v1(-155,421) C26.2@-155,451.47 ; CN9.32@900,400 953,347 953,76 923,46 525,46 183,388 -55,388 -84,417 C28.2@-84,451.47 C26.2@-155,451.47
  Bottom Layer w15: v1(-282,567) -272,557 SB4.2@-272,517.5 -233.5,517.5 -155,439 v1(-155,421)
AIN_1: R1.2 R2.2 U1.10 | length 242.1
  Top Layer w10: R1.2@-1068.5,2352 R2.2@-1068.5,2413 ; R2.2@-1068.5,2417 R2.2@-1068.5,2413 ; U1.10@-923.35,2490.1 -960.9,2490.1 -1038,2413 R2.2@-1068.5,2413
E5V: CN1.6 D2.2 JP2.5 | length 2687.3
  Top Layer w20: v2(-1103,1683) v1(-1103,1713) ; JP2.5@-255,1465.67 -255,1516 -223,1548 -149,1548 -101.87,1595.13 v1(-101.87,1733.87) v1(-101.87,1765.13) ; v1(-94,1956) -94,2185 -64,2215 88,2215 147.21,2274.21 D2.2@147.21,2336
  Top Layer w30: v1(-1103,1713) -1050.87,1765.13 v1(-101.87,1765.13)
  Bottom Layer w20: v2(-1103,1683) v1(-1103,1713) ; v1(-101.87,1733.87) v1(-101.87,1765.13) -101.87,1948.13 v1(-94,1956)
  Bottom Layer w30: CN1.6@-1500,1700 -1483,1683 v2(-1103,1683)
FAULT: LD3.1 R33.1 U7.8 | length 224.7
  Top Layer w10: R33.1@500,2411.5 LD3.1@565,2411.5 565,2450.1 555,2460.1 555,2515.24 U7.8@518.39,2551.85
GND: B1.3 B1.4 B2.3 B2.4 C1.1 C2.1 C3.2 C4.2 C6.1 C7.1 C8.1 C9.1 C10.1 C11.1 C12.2 C13.2 C14.1 C15.1 C16.1 C17.1 C18.1 C19.1 C20.1 C21.1 C22.1 C23.1 C24.2 C27.1 C29.1 C30.2 C31.2 C32.1 C33.1 C34.1 C35.2 CN1.8 CN1.19 CN1.20 CN1.22 CN2.3 CN3.1 CN3.2 CN5.6 CN5.7 CN6.5 CN6.6 CN6.7 CN6.8 CN6.9 CN6.10 CN6.11 CN8.7 CN9.9 CN9.20 CN10.1 CN10.2 JP1.1 LD1.1 LD4.1 Q1.2 R1.1 R3.1 R5.1 R7.1 R11.1 R18.2 R22.1 R25.1 R28.1 R29.1 SB4.1 U1.8 U1.20 U1.23 U1.35 U1.47 U2.2 U2.7 U3.10 U3.30 U3.56 U4.2 U5.1 U6.2 U7.4 U7.9 | length 6269
  Top Layer w8: v1(-653,843) -648.26,843 -631.42,859.84 U3.56@-529.41,859.84 ; U6.2@138,2844.46 v1(138,2875)
  Top Layer w10: U1.8@-923.35,2529.47 -866.47,2529.47 v1(-866,2529) v1(-866,2529) v1@-865.47,2529.47 ; v1(-847,2675) -846.58,2675.42 U1.47@-846.58,2724.35 ; v1(-729,2341) -728.47,2341.53 U1.20@-728.47,2393.65 ; v1(-671,2336) -669.42,2337.58 U1.23@-669.42,2393.65 ; v1(-647,2651) -643.58,2647.58 U1.35@-592.65,2647.58 ; U3.10@-275.47,625.59 -275.47,664.53 v2(-256,684) ; U3.30@-80.59,958.27 -23.73,958.27 v1(-17,965) ; C31.2@100.5,960 v1(132,960)
  Top Layer w12: v1(-1084,1904) -1034,1954 R5.1@-999.5,1954 ; C15.1@-686.5,2290 -686.5,2320.5 v1(-671,2336) ; v1(-653,843) v1(-836,843) -866,843 -883,860 v1(-883,990) -883,1034 -912,1063 -1121,1063 -1152,1032 -1152,764 -1041,653 -647,653 -622,678 -622,713 v1(-596,739) ; Q1.2@-491.6,1245.72 -491.6,1216.6 -491,1216 v1(-491,1212) ; v1(-473,555) -504,555 -547,512 -547,108 -527,88 v1(-490,88) v1(-375,88) -361,88 -341,108 -341,380.63 -361.37,401 -361.37,547.37 v1(-371,557) ; v1(-446,1220) -446,1240.5 R22.1@-433,1253.5 ; C24.2@-299,451.47 -287,439.47 v1(-287,417) ; R25.1@-228,2775.99 v1(-228,2807) ; v1(21,2781) 54.5,2781 55.5,2780 R28.1@56,2780.5 ; v1(70,2910) 73.82,2913.82 CN6.5@73.82,2965 CN6.5@73.82,2990
  Top Layer w15: v1(-1493,3026) v1@-1492.5,3025.5 ; v1(-1174,2557) -1173,2556 v1(-1090,2556) -1045,2556 -1039,2550 v1(-987,2550) ; v1(-1167,2700) C4.2@-1131.5,2700 ; v1(-1166.5,2492) C2.1@-1131.5,2492 C2.1@-1128.99,2492 ; v1(-1166,2625) C3.2@-1131.5,2625 ; v1(-1154,2819) -1117,2819 v1(-1062,2764) -1010,2712 v1(-1010,2700) -1010,2637 v1(-982,2609) ; v1(-1140,2317) -1140,2343.5 R1.1@-1131.5,2352 ; R3.1@-1055,2889.5 v1(-1055,2927) ; R7.1@-986.17,2889.5 -986.17,2924.83 v1(-986,2925) ; v1(-929,1458) U2.2@-890.09,1458 ; C6.1@-917.33,2889.5 -917.33,2925.67 -917,2926 v1(-917,2927) ; B1.3@-850.28,2023.58 -788.58,2023.58 v1(-788,2023) ; v1(-844,1221) C7.1@-844,1256.5 C10.1@-776,1256.5 v1(-776,1221) ; v1(-780,2923) -779,2923 -779.67,2922.33 R11.1@-779.67,2889.5 ; R18.2@-642,2889.5 v1(-642,2926) ; B1.4@-509.72,2023.58 -454.42,2023.58 v1(-454,2024) ; v1(-491,2475) C21.1@-456.5,2475 ; C23.1@-382,1956.5 v1(-382,1993) ; v1(-326,2024) -325.58,2023.58 B2.3@-270.28,2023.58 ; B2.4@70.28,2023.58 121.42,2023.58 v1(122,2023) ; v1(360,2315) R29.1@360,2348.5 ; U7.4@405,2711.3 v1(405,2761) ; v1(435,2316) C34.1@435,2348.5 ; C35.2@550,2856.5 v1(550,2891) ; 719.85,3028.15 720,3028
  Top Layer w20: v1(-916,1565) LD1.1@-916,1598.5 ; v1(-849,1528) -849,1474 U2.7@-833,1458 -818,1473 v1(-818,1528) ; C11.1@-775,1661.5 v1(-775,1697) ; C14.1@-715,1661.5 v1(-715,1700) ; v1(-490,2405) C20.1@-456.5,2405 ; v1(-489,2340) C19.1@-456.5,2340 ; v1(-488,2275) C18.1@-456.5,2275 ; v1(-264,2335) -264.12,2335.13 v1(-264.12,2368.13) -264,2368 U4.2@-212.82,2368 ; C27.1@-116,2398.5 v1(-116,2435) ; C29.1@-49,2398.5 v1(-49,2433) ; v1(191,1484) 191.45,1484.45 U5.1@245.08,1484.45 ; v1(335,1470) 339,1474 C33.1@339,1521.52 ; C33.1@345,1518 C33.1@350.52,1518
  Top Layer w25: v1(-494,2777) -456.01,2777 C17.1@-455,2775.99 ; CN6.9@-12.8,3096.3 CN6.8@262.8,3096.3
  Bottom Layer w12: v1(-287,417) -287,435 SB4.1@-272,450 -272,445 SB4.1@-267,450
  other v1: -1160,-65 -1040,-65 -920,-65 -800,-65 -680,-65 -560,-65 -440,-65 -320,-65 -200,-65 -80,-65 125,-20 230,10 340.83,10 451.67,10 562.5,10 673.33,10 784.17,10 895,10 -1560,15 -1415,15 -1260,15 -1137,18 -1675,35 985,35 -921,38 -1020,45 -145,45 160,87 -1065,90 -665,90 -570,90 -975,93 335,99 -1145,110 -80,111 -1700,115 66,116 1000,125 -200,130 -535,134 -746,137 -629,137 -335,140 -535,210 -1700,225.83 -336,229 1000,235.28 -200,245 -80,245 -402,258 -476,259 515,310 -1700,336.67 1000,345.56 445,370 385,430 -927,445 -1700,447.5 1000,455.83 -959,468 -900,470 345,470 -1700,558.33 1000,566.11 240,600 -35,625 -880,640 -950,645 -105,645 195,645 -1700,669.17 1000,676.39 -1070,690 150,690 -880,720 -210,735 -265,770 -1700,780 1000,786.67 -878,797 -580,805 -755,840 -1125,850 -915,855 -1700,890.83 1000,896.94 -1125,930 -915,935 235,955 -1700,1001.67 1000,1007.22 400,1010 144,1032 77,1033 217,1034 -885,1045 -1085,1055 -1020,1055 -945,1055 690,1105 -1700,1112.5 1000,1117.5 -480,1135 -560,1175 670,1200 -665,1220 -1700,1223.33 1000,1227.78 -1700,1334.17 1000,1338.05 10,1435 230,1435 -1700,1445 50,1445 1000,1448.33 386,1522 -1700,1555.83 1000,1558.61 130,1650 -1700,1666.67 1000,1668.89 -15,1675 95,1735 -15,1750 -1700,1777.5 1000,1779.17 -990,1820 -1060,1835 339,1851 310,1885 -1700,1888.33 1000,1889.44 -1355,1930 -680,1935 -570,1935 -445,1935 -800,1940 -25,1950 -1200,1995 -1700,1999.17 1000,1999.72 -1444,2020 -20,2020 -645,2025 -1180,2105 -1700,2110 -1575,2110 -1455,2110 1000,2110 -960,2115 -885,2115 -815,2115 -530,2115 -445,2115 -345,2115 -270,2115 50,2115 105,2115 165,2115 220,2115 -1600,2212 -1510.2,2212 -1420.4,2212 -1330.6,2212 -1240.8,2212 -1151,2212 -370,2212 -266,2212 -1700,2213 684,2213 787.33,2213 890.67,2213 1000,2213 -960,2215 -879,2215 -798,2215 -717,2215 235,2216 150,2219 -764,2261 -840,2276 204,2289 -1700,2304.44 1000,2313.38 295,2365 -1700,2395.89 1000,2414.75 734,2443 -843,2448 298,2454 -655,2456 -769,2469 -1700,2487.33 -93,2498 -187,2507 192,2513 1000,2516.13 -655,2517 30,2519 703,2522 -730,2527 340,2527 -508,2570 -1700,2578.78 -655,2585 -442,2590 -380,2590 -322,2590 -255,2590 -189,2590 -117,2590 -41,2590 38,2590 117,2590 928,2600 291,2601 786,2601 408,2605 560,2605 -809,2608 1000,2617.5 157,2623 -535,2636 708,2637 -419,2652 -375,2652 -323,2652 -250,2652 -182,2652 -118,2652 8,2652 -1702,2654 408,2657 107,2662 166,2663 262,2668 1000,2718.88 710,2753 -1700,2761.67 93,2781 276,2786 186,2796 1000,2820.25 -1700,2853.11 -49,2855 184,2855 -425,2858 94,2858 755,2876 272,2885 -522,2887 -114,2895 -1184,2909 1000,2921.63 572,2924 -1700,2944.56 -54,2948 -245,2952 -150,2954 -341,2958 -1118,2959 316,2976 -513,2994 -1000,3021 -892,3021 1000,3023 -414,3026 -1700,3036 381,3058 -1683,3106 980,3108 329,3120 423.17,3120 517.33,3120 611.5,3120 705.67,3120 799.83,3120 894,3120 -600.2,3121 -496.4,3121 -392.6,3121 -288.8,3121 -185,3121 -81.2,3121 -1601.43,3123 -1500.57,3123 -1399.71,3123 -1298.86,3123 -1198,3123 -1097.14,3123 -996.29,3123 -895.43,3123
  other v3: 458.35,2583.35 501.65,2583.35 458.35,2626.65 501.65,2626.65
LED_STLINK: R31.2 R32.2 U1.30 | length 1406.2
  Top Layer w5: U1.30@-592.65,2549.16 -494.84,2549.16 -477,2567 197,2567 304,2674 304,2839 399,2934 R31.2@463.5,2934 R32.2@463.5,3028
NetB1_1: B1.1 B1.2 C5.2 R6.1 SB18.2 | length 2155.5
  Top Layer w5: v1(-742,1158) -748,1152 -1087,1152 -1158,1223 -1158,1874 -1041,1991 -946,1991 -936.5,2000.5 R6.1@-936.5,2027 -900,1990.5 -900,1914.5 C5.2@-936.5,1878 -904.92,1846.42 B1.2@-850.28,1846.42 B1.1@-509.72,1846.42
  Bottom Layer w5: v1(-742,1158) -741.75,1157.75 SB18.2@-741.75,1039 SB18.2@-729,1051.75
NetC5_1: C5.1 R5.2 | length 129.6
  Top Layer w5: C5.1@-1003.5,1878 -1003.5,1908.5 -996,1916 -949,1916 -940.5,1924.5 R5.2@-940.5,1954
NetC7_2: C7.2 C10.2 SB19.1 U2.4 | length 68
  Top Layer w20: C7.2@-844,1319.5 C10.2@-776,1319.5
  other v1: -951,1362 -918,1363 -883,1363
NetC8_2: C8.2 R13.2 X2.4 | length 459.4
  Top Layer w5: X2.4@-1067.99,781.73 -1067.99,741.99 -1005,679 -794,679 -782.5,690.5 C8.2@-782.5,719 R13.2@-722.5,719 ; R13.2@-724.5,719 -722.5,717 R13.2@-710.5,717
NetC9_2: C9.2 R14.2 X2.1 | length 269.9
  Top Layer w5: X2.1@-942.01,781.73 -922.28,762 -789,762 -782.5,768.5 C9.2@-782.5,797 R14.2@-722.5,797 R14.2@-711.5,797
NetC16_2: C16.2 R20.1 X3.2 | length 320.7
  Top Layer w5: X3.2@-477.4,181 -477.4,203.4 -516,242 -516,354 -504.5,365.5 C16.2@-475,365.5 R20.1@-475,451.47
NetC20_2: C20.2 U4.4 | length 78.5
  Top Layer w20: C20.2@-393.5,2405 -393.1,2405.4 U4.4@-315.18,2405.4
NetC22_2: C22.2 R23.2 X3.1 | length 319.5
  Top Layer w5: R23.2@-406,451.47 C22.2@-406,365.5 -376.5,365.5 -366,355 -366,244 -402.6,207.4 X3.1@-402.6,181
NetC27_2: C27.2 C29.2 D2.1 D3.1 D4.1 U4.1 U4.3 | length 67
  Top Layer w20: C27.2@-116,2335.5 C29.2@-49,2335.5
NetCN1_15: CN1.15 SB17.2 | length 1428.4
  Top Layer w5: CN1.15@-1600,1200 -1549,1149 -1549,1072 -1528,1051 -1241,1051 -1192,1002 -1192,752 -1041,601 -857,601 v1(-843,615)
  Bottom Layer w5: v1(-843,615) -843,697.75 SB17.2@-741.75,799
NetCN1_17: CN1.17 SB16.2 | length 1310
  Top Layer w5: CN1.17@-1600,1100 -1600,1076 -1549,1025 -1549,970 -1530,951 -1275,951 -1211,887 -1211,748 -1046,583 -841,583 v1(-808,616)
  Bottom Layer w5: v1(-808,616) -808,698 -773.72,732.28 SB16.2@-741.75,732.28
NetCN1_25: CN1.25 SB8.2 | length 1448.1
  Top Layer w5: CN1.25@-1600,700 -1551,651 -1265,651 -956,342 -956,302 -884,230 v1(-884,227)
  Bottom Layer w5: v1(-884,227) -642,227 -550,319 -550,431 SB8.2@-531,450
NetCN1_27: CN1.27 SB6.2 | length 1913
  Top Layer w5: CN1.27@-1600,600 -1557,557 -1244,557 -741,54 -347,54 -307,94 -307,343 v1(-316,352)
  Bottom Layer w5: SB6.2@-358.33,450 -358.33,394.33 v1(-316,352)
NetCN1_36: CN1.36 CN4.5 SB14.2 SB15.1 | length 1008.2
  Top Layer w5: CN1.36@-1500,200 CN4.5@-1300,200 -1102,200 v1(-1097,205)
  Bottom Layer w5: v1(-1097,205) -794,508 -794,546.61 SB14.2@-741.75,598.86 SB15.1@-741.75,661
NetCN1_38: CN1.38 CN4.6 SB12.2 SB13.1 | length 1000.6
  Top Layer w5: CN1.38@-1500,100 CN4.6@-1300,100 -1238,100 -1193,145 v1(-1073,145)
  Bottom Layer w5: v1(-1073,145) -1073,202 -809.57,465.43 SB12.2@-741.75,465.43 SB13.1@-741.75,523
NetCN5_1: CN5.1 R4.1 | length 324.5
  Top Layer w15: v1(-1106,1600) -1027.5,1600 -1024.5,1603 R4.1@-1020,1598.5
  Bottom Layer w15: CN5.1@-1300,1500 -1200,1600 v1(-1106,1600)
NetCN6_4: CN6.4 R28.2 | length 164.5
  Top Layer w5: R28.2@56,2843.5 66,2853.5 66,2869 99.41,2902.41 CN6.4@99.41,2965 CN6.4@99.41,2990
NetD1_1: D1.1 R19.1 | length 82.3
  Top Layer w5: R19.1@-642,3025.5 -624.28,3043.21 D1.1@-567,3043.21
NetLD1_2: LD1.2 R10.1 | length 71
  Top Layer w10: LD1.2@-916,1661.5 R10.1@-845,1661.5
NetLD2_1: LD2.1 Q1.3 | length 104.5
  Top Layer w12: LD2.1@-627,1320.5 -611.22,1336.28 Q1.3@-529,1336.28
NetLD2_2: LD2.2 R17.2 | length 66
  Top Layer w5: R17.2@-693,1257.5 LD2.2@-627,1257.5
NetLD3_2: LD3.2 R34.1 | length 70
  Top Layer w10: LD3.2@565,2348.5 R34.1@635,2348.5
NetLD4_2: LD4.2 R32.1 | length 97.1
  Top Layer w5: R32.1@526.5,3028 LD4.2@613.32,3028 ; LD4.2@615.47,3030.15 LD4.2@613.32,3028 ; LD4.2@620.47,3028.15 620.32,3028 LD4.2@613.32,3028
NetLD4_3: LD4.3 R31.1 | length 195.3
  Top Layer w5: R31.1@526.5,2934 569.5,2977 634,2977 674.53,3017.53 LD4.3@674.53,3030.15
NetQ1_1: Q1.1 R22.2 SB5.2 | length 252.1
  Top Layer w5: Q1.1@-566.4,1245.72 -543.28,1245.72 -472.5,1316.5 R22.2@-433,1316.5 -432.5,1317 v1(-387,1317)
  Bottom Layer w5: v1(-387,1317) -384.25,1319.75 SB5.2@-345,1319.75
NetQ2_1: Q2.1 R24.1 R25.2 R26.2 | length 204.7
  Top Layer w5: R24.1@-293,2713 R25.2@-228,2713 R26.2@-163,2713 -126,2713 -113.72,2700.72 Q2.1@-93.4,2700.72
NetQ2_2: Q2.2 R27.1 | length 71.6
  Top Layer w5: Q2.2@-18.6,2700.72 52.23,2700.72 R27.1@52.5,2701
  Top Layer w12: Q2.2@-18.6,2700.72 Q2.2@-18.32,2701
NetR3_2: R3.2 U1.3 | length 281
  Top Layer w5: R3.2@-1055,2826.5 -1055,2794 -987,2726 -987,2644 -971.37,2628.37 -923.83,2628.37 U1.3@-923.35,2627.9
NetR7_2: R7.2 U1.2 | length 227.3
  Top Layer w5: R7.2@-986.17,2826.5 -986.17,2767.17 -971,2752 -971,2657 -961.58,2647.58 U1.2@-923.35,2647.58
NetR11_2: R11.2 U1.44 | length 105.4
  Top Layer w5: U1.44@-787.53,2724.35 -787.53,2772.47 -779.67,2780.33 R11.2@-779.67,2826.5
